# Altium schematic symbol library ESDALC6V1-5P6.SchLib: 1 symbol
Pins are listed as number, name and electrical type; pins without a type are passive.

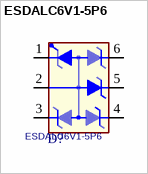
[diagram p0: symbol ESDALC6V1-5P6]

## ESDALC6V1-5P6
designator D?
footprint ST_SOT666
pins: 1, 2 GND, 3, 4, 5, 6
